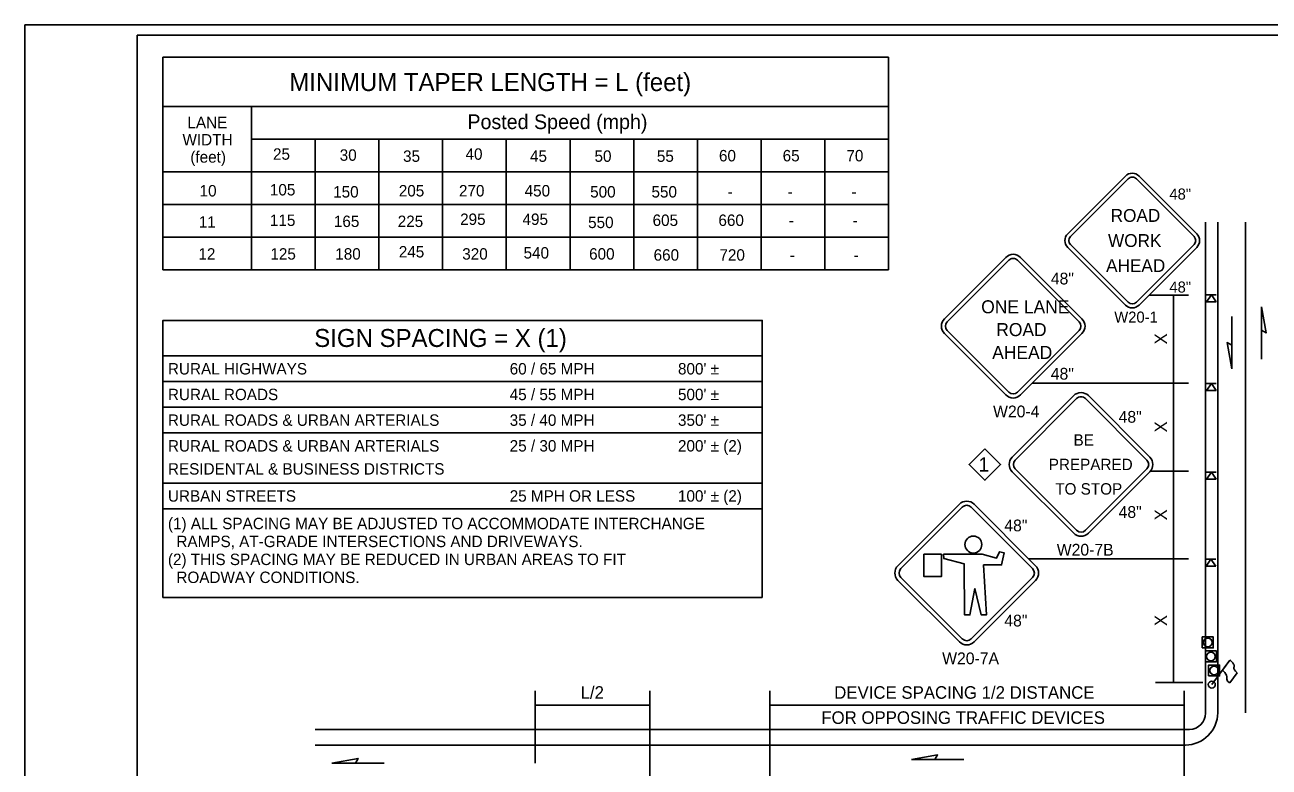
# Model space of a CAD drawing. Extents: x 99988 to 100172, y 99995 to 100047.
# Drawn here: x 99999.31 to 100006.94, y 100005.89 to 100010.44 of the extents above; entities that cross this region are included whole.
import ezdxf

# ---------------------------------------------------------------- set-up
doc = ezdxf.new("R2010")
doc.units = 0
for name, color, linetype in [('Default', 7, 'Continuous'), ('Level 15', 7, 'Continuous'), ('Level 20', 7, 'Continuous'), ('SH_DE_DetailBody1Text', 7, 'Continuous'), ('SH_GI_PlotLimits', 7, 'Continuous'), ('SH_GI_SheetBorder', 7, 'Continuous'), ('SH_GI_TrafficMvmntArrowRt1Lane', 7, 'Continuous'), ('SH_TI_MinTaperLength25to70Note', 7, 'Continuous'), ('SH_TI_SignSpacing35to70Note', 7, 'Continuous'), ('TR_SN_WarningSigns', 7, 'Continuous'), ('TR_WZ_FlaggingStation', 7, 'Continuous'), ('TR_WZ_TrafficSafetyCone', 7, 'Continuous'), ('TR_WZ_WorkZoneDetails', 7, 'Continuous')]:
    doc.layers.add(name, color=color, linetype=linetype)

msp = doc.modelspace()

# ---------------------------------------------------------------- linework, layer by layer
at = {"layer": 'Default'}
for p, q in [((100006.5586, 100008.7401), (100006.588, 100008.7825)), ((100006.5586, 100008.7825), (100006.6176, 100008.7825)), ((100006.5586, 100008.7401), (100006.6176, 100008.7401)), ((100006.6176, 100008.7401), (100006.588, 100008.7825)), ((100006.5586, 100008.1966), (100006.588, 100008.2389)), ((100006.5586, 100008.2389), (100006.6176, 100008.2389)), ((100006.5586, 100008.1966), (100006.6176, 100008.1966)), ((100006.6176, 100008.1966), (100006.588, 100008.2389)), ((100006.5586, 100007.653), (100006.588, 100007.6954)), ((100006.5586, 100007.6954), (100006.6176, 100007.6954)), ((100006.5586, 100007.653), (100006.6176, 100007.653)), ((100006.6176, 100007.653), (100006.588, 100007.6954)), ((100006.5553, 100007.1193), (100006.5848, 100007.1616)), ((100006.5553, 100007.1616), (100006.6143, 100007.1616)), ((100006.5553, 100007.1193), (100006.6143, 100007.1193)), ((100006.6143, 100007.1193), (100006.5848, 100007.1616))]:
    msp.add_line(p, q, dxfattribs=at)
at = {"layer": 'Level 15'}
for p, q in [((100006.355, 100008.781), (100006.355, 100008.5112)), ((100006.355, 100008.2414), (100006.355, 100008.5112)), ((100006.355, 100008.2414), (100006.355, 100007.9715)), ((100006.355, 100007.7017), (100006.355, 100007.9715)), ((100006.355, 100007.7017), (100006.355, 100007.4325)), ((100006.355, 100007.1633), (100006.355, 100007.4325)), ((100006.355, 100007.1633), (100006.355, 100006.7845)), ((100006.355, 100006.4057), (100006.355, 100006.7845)), ((100002.4418, 100006.2679), (100002.7935, 100006.2679)), ((100003.1451, 100006.2679), (100002.7935, 100006.2679)), ((100003.8812, 100006.2679), (100005.1513, 100006.2679)), ((100006.4214, 100006.2679), (100005.1513, 100006.2679))]:
    msp.add_line(p, q, dxfattribs=at)
at = {"layer": 'SH_DE_DetailBody1Text'}
msp.add_lwpolyline([(100005.1993, 100007.8395), (100005.2958, 100007.743), (100005.1993, 100007.6465), (100005.1027, 100007.743)], close=True, dxfattribs=at)
at = {"layer": 'SH_GI_PlotLimits'}
msp.add_lwpolyline([(99999.3125, 99999.9375), (100015.8125, 99999.9375), (100015.8125, 100010.4375), (99999.3125, 100010.4375)], close=True, dxfattribs=at)
at = {"layer": 'SH_GI_SheetBorder'}
for q in [(100000, 100000), (100015.75, 100010.375)]:
    msp.add_line((100000, 100010.375), q, dxfattribs=at)
at = {"layer": 'SH_GI_TrafficMvmntArrowRt1Lane'}
for p, q in [((100006.7126, 100008.4735), (100006.7126, 100008.6503)), ((100006.8951, 100008.5653), (100006.8951, 100008.3885)), ((100001.3398, 100005.9121), (100001.5166, 100005.9121)), ((100004.8932, 100005.9336), (100005.07, 100005.9336))]:
    msp.add_line(p, q, dxfattribs=at)
for points in [[(100006.8951, 100008.7095), (100006.9234, 100008.549), (100006.8951, 100008.5653)], [(100006.7126, 100008.3294), (100006.6844, 100008.4898), (100006.7126, 100008.4735)], [(100001.1957, 100005.9121), (100001.3561, 100005.9404), (100001.3398, 100005.9121)], [(100004.749, 100005.9336), (100004.9095, 100005.9618), (100004.8932, 100005.9336)]]:
    msp.add_lwpolyline(points, close=True, dxfattribs=at)
at = {"layer": 'SH_TI_MinTaperLength25to70Note'}
for p, q in [((100000.1587, 100009.9363), (100004.6087, 100009.9363)), ((100000.7018, 100009.4812), (100000.7018, 100009.9363)), ((100000.7018, 100009.7363), (100004.6087, 100009.7363)), ((100001.0925, 100009.7363), (100001.0925, 100008.9363)), ((100001.4832, 100009.7363), (100001.4832, 100008.9363)), ((100001.8739, 100009.7363), (100001.8739, 100008.9363)), ((100002.2646, 100009.7363), (100002.2646, 100008.9363)), ((100002.6553, 100009.7363), (100002.6553, 100008.9363)), ((100003.0459, 100009.7363), (100003.0459, 100008.9363)), ((100003.4366, 100009.7363), (100003.4366, 100008.9363)), ((100003.8273, 100009.7363), (100003.8273, 100008.9363)), ((100004.2179, 100009.7363), (100004.2179, 100008.9363)), ((100000.1587, 100009.5363), (100004.6087, 100009.5363)), ((100000.7018, 100009.4812), (100000.7018, 100008.9363)), ((100000.1587, 100009.3363), (100004.6087, 100009.3363)), ((100000.1587, 100009.1363), (100004.6087, 100009.1363))]:
    msp.add_line(p, q, dxfattribs=at)
at = {"layer": 'SH_TI_SignSpacing35to70Note'}
for p, q in [((100000.1587, 100010.2395), (100004.6087, 100010.2395)), ((100000.1587, 100009.4812), (100000.1587, 100010.2395)), ((100004.6087, 100010.2395), (100004.6087, 100008.9363)), ((100000.1587, 100009.4812), (100000.1587, 100008.9363)), ((100000.1587, 100008.9363), (100004.6087, 100008.9363)), ((100000.1587, 100008.4081), (100003.8342, 100008.4081)), ((100000.1587, 100008.2507), (100003.8342, 100008.2507)), ((100000.1587, 100008.0933), (100003.8342, 100008.0933)), ((100000.1587, 100007.9359), (100003.8342, 100007.9359)), ((100000.1587, 100007.6284), (100003.8342, 100007.6284)), ((100000.1587, 100007.471), (100003.8342, 100007.471)), ((100000.1587, 100006.9274), (100003.8342, 100006.9274))]:
    msp.add_line(p, q, dxfattribs=at)
for points in [[(100000.1587, 100008.4114), (100000.1587, 100008.6254), (100003.8342, 100008.6254), (100003.8342, 100008.4114)], [(100000.1587, 100006.9274), (100000.1587, 100008.4108)], [(100003.8342, 100008.4123), (100003.8342, 100006.9274)]]:
    msp.add_lwpolyline(points, dxfattribs=at)
at = {"layer": 'TR_SN_WarningSigns'}
for p, q in [((100005.7074, 100009.1576), (100006.0608, 100009.511)), ((100005.7242, 100009.1408), (100006.0776, 100009.4942)), ((100006.1281, 100009.4942), (100006.4815, 100009.1408)), ((100006.1449, 100009.511), (100006.4983, 100009.1576)), ((100006.0608, 100008.7201), (100005.7074, 100009.0735)), ((100006.0776, 100008.7369), (100005.7242, 100009.0903)), ((100006.4815, 100009.0903), (100006.1281, 100008.7369)), ((100006.4983, 100009.0735), (100006.1449, 100008.7201)), ((100004.9509, 100008.6355), (100005.3278, 100009.0125)), ((100004.9688, 100008.6176), (100005.3458, 100008.9945)), ((100005.3996, 100008.9945), (100005.7766, 100008.6176)), ((100005.4176, 100009.0125), (100005.7945, 100008.6355)), ((100005.3458, 100008.1868), (100004.9688, 100008.5637)), ((100005.7766, 100008.5637), (100005.3996, 100008.1868)), ((100005.3278, 100008.1688), (100004.9509, 100008.5458)), ((100005.7945, 100008.5458), (100005.4176, 100008.1688)), ((100005.3668, 100007.7879), (100005.7438, 100008.1648)), ((100005.3848, 100007.7699), (100005.7617, 100008.1469)), ((100005.8156, 100008.1469), (100006.1925, 100007.7699)), ((100005.8335, 100008.1648), (100006.2105, 100007.7879)), ((100005.7438, 100007.3212), (100005.3668, 100007.6981)), ((100005.7617, 100007.3391), (100005.3848, 100007.7161)), ((100006.1925, 100007.7161), (100005.8156, 100007.3391)), ((100006.2105, 100007.6981), (100005.8335, 100007.3212)), ((100004.6659, 100007.1221), (100005.0428, 100007.4991)), ((100005.1326, 100007.4991), (100005.5095, 100007.1221)), ((100004.6838, 100007.1042), (100005.0608, 100007.4812)), ((100005.1146, 100007.4812), (100005.4916, 100007.1042)), ((100005.0428, 100006.6555), (100004.6659, 100007.0324)), ((100005.0608, 100006.6734), (100004.6838, 100007.0503)), ((100005.4916, 100007.0503), (100005.1146, 100006.6734)), ((100005.5095, 100007.0324), (100005.1326, 100006.6555))]:
    msp.add_line(p, q, dxfattribs=at)
for points in [[(100004.8252, 100007.1927), (100004.8252, 100007.0555), (100004.9322, 100007.0555), (100004.9322, 100007.1927)], [(100004.9448, 100007.193), (100004.9464, 100007.1666), (100005.0717, 100007.1337), (100005.0744, 100006.8208), (100005.107, 100006.8208), (100005.138, 100006.9819), (100005.1771, 100006.8205), (100005.2086, 100006.8205), (100005.1907, 100007.1273), (100005.3019, 100007.1273), (100005.317, 100007.2018), (100005.2888, 100007.2072), (100005.2707, 100007.1691), (100005.1822, 100007.193)]]:
    msp.add_lwpolyline(points, close=True, dxfattribs=at)
msp.add_circle((100005.1285, 100007.2518), 0.0519, dxfattribs=at)
for centre, radius, start, end in [((100006.1029, 100009.4689), 0.0595, 44.99628, 134.99965), ((100006.1029, 100009.4689), 0.0357, 44.99628, 134.99965), ((100005.7495, 100009.1155), 0.0595, 134.99658, 224.99358), ((100005.7495, 100009.1155), 0.0357, 134.99658, 224.99358), ((100006.4562, 100009.1155), 0.0357, 314.99936, 44.99485), ((100006.4562, 100009.1155), 0.0595, 314.99936, 44.99485), ((100005.3727, 100008.9676), 0.0635, 44.99628, 134.99965), ((100005.3727, 100008.9676), 0.0381, 44.99628, 134.99965), ((100006.1028, 100008.7622), 0.0595, 225, 314.99958), ((100006.1028, 100008.7622), 0.0357, 225, 314.99958), ((100004.9958, 100008.5906), 0.0635, 134.99658, 224.99358), ((100005.7497, 100008.5906), 0.0635, 314.99936, 44.99485), ((100004.9958, 100008.5906), 0.0381, 134.99658, 224.99358), ((100005.7497, 100008.5906), 0.0381, 314.99936, 44.99485), ((100005.3727, 100008.2137), 0.0381, 225, 314.99958), ((100005.7886, 100008.1199), 0.0635, 44.99628, 134.99965), ((100005.3727, 100008.2137), 0.0635, 225, 314.99958), ((100005.7886, 100008.1199), 0.0381, 44.99628, 134.99965), ((100005.4117, 100007.743), 0.0635, 134.99658, 224.99358), ((100005.4117, 100007.743), 0.0381, 134.99658, 224.99358), ((100006.1656, 100007.743), 0.0381, 314.99936, 44.99485), ((100006.1656, 100007.743), 0.0635, 314.99936, 44.99485), ((100005.0877, 100007.4542), 0.0635, 44.99628, 134.99965), ((100005.0877, 100007.4542), 0.0381, 44.99628, 134.99965), ((100005.7886, 100007.3661), 0.0381, 225, 314.99958), ((100005.7886, 100007.3661), 0.0635, 225, 314.99958), ((100004.7107, 100007.0773), 0.0635, 134.99658, 224.99358), ((100005.4646, 100007.0773), 0.0635, 314.99936, 44.99485), ((100004.7107, 100007.0773), 0.0381, 134.99658, 224.99358), ((100005.4646, 100007.0773), 0.0381, 314.99936, 44.99485), ((100005.0877, 100006.7003), 0.0635, 225, 314.99958), ((100005.0877, 100006.7003), 0.0381, 225, 314.99958)]:
    msp.add_arc(centre, radius, start, end, dxfattribs=at)
at = {"layer": 'TR_WZ_FlaggingStation'}
for p, q in [((100006.5906, 100006.3933), (100006.7016, 100006.5433)), ((100006.6566, 100006.4824), (100006.7018, 100006.5435)), ((100006.6566, 100006.4824), (100006.6566, 100006.4824)), ((100006.7468, 100006.4658), (100006.7005, 100006.4032))]:
    msp.add_line(p, q, dxfattribs=at)
for points in [[(100006.7018, 100006.5435), (100006.7046, 100006.5408), (100006.7137, 100006.533), (100006.7202, 100006.526), (100006.7237, 100006.5194), (100006.727, 100006.5139), (100006.728, 100006.5081), (100006.7279, 100006.5022), (100006.7261, 100006.4985), (100006.7262, 100006.4915), (100006.7299, 100006.4836), (100006.7352, 100006.4766), (100006.7468, 100006.4658)], [(100006.7005, 100006.4032), (100006.6963, 100006.4067), (100006.6877, 100006.4152), (100006.6823, 100006.4263), (100006.682, 100006.4345), (100006.6832, 100006.4417), (100006.6816, 100006.4509), (100006.6774, 100006.4581), (100006.6698, 100006.4679), (100006.6566, 100006.4824)]]:
    msp.add_lwpolyline(points, dxfattribs=at)
msp.add_circle((100006.5906, 100006.3933), 0.0214, dxfattribs=at)
at = {"layer": 'TR_WZ_TrafficSafetyCone'}
for points in [[(100006.5322, 100006.6185), (100006.599, 100006.6185), (100006.599, 100006.6853), (100006.5322, 100006.6853)], [(100006.5517, 100006.5325), (100006.6186, 100006.5325), (100006.6186, 100006.5993), (100006.5517, 100006.5993)], [(100006.5713, 100006.4465), (100006.6381, 100006.4465), (100006.6381, 100006.5133), (100006.5713, 100006.5133)]]:
    msp.add_lwpolyline(points, close=True, dxfattribs=at)
for centre in [(100006.5656, 100006.6519), (100006.5851, 100006.5659), (100006.6047, 100006.4799)]:
    msp.add_circle(centre, 0.0268, dxfattribs=at)
at = {"layer": 'TR_WZ_WorkZoneDetails'}
for p, q in [((100006.5524, 100006.2179), (100006.5524, 100009.2274)), ((100006.6267, 100006.2209), (100006.6267, 100009.2274)), ((100006.797, 100006.2209), (100006.797, 100009.2274)), ((100006.4486, 100008.781), (100006.2059, 100008.781)), ((100006.4486, 100008.2414), (100005.4901, 100008.2414)), ((100006.4486, 100007.7017), (100006.2138, 100007.7017)), ((100006.4486, 100007.1633), (100005.4684, 100007.1633)), ((100002.4418, 100005.9119), (100002.4418, 100006.3559)), ((100003.1451, 100005.7776), (100003.1451, 100006.3559)), ((100003.8812, 100005.6997), (100003.8812, 100006.3559)), ((100006.5347, 100006.4057), (100006.245, 100006.4057)), ((100006.4214, 100005.7046), (100006.4214, 100006.3559)), ((100001.0926, 100006.1188), (100002.7834, 100006.1188)), ((100002.281, 100006.1188), (100006.4533, 100006.1188)), ((100001.0926, 100006.0228), (100002.7834, 100006.0228)), ((100002.281, 100006.0228), (100006.4285, 100006.0228))]:
    msp.add_line(p, q, dxfattribs=at)
for centre, radius in [((100006.4285, 100006.2209), 0.1982), ((100006.4533, 100006.2179), 0.0991)]:
    msp.add_arc(centre, radius, 270, 360, dxfattribs=at)

# ---------------------------------------------------------------- texts
at = {"layer": 'Level 20'}
for s, rotation, p in [('X', 90, (100006.3165, 100008.4785)), ('X', 90, (100006.3165, 100007.9389)), ('X', 90, (100006.3165, 100007.3998)), ('X', 90, (100006.3165, 100006.7518)), ('L/2', 360, (100002.7201, 100006.3064)), ('DEVICE SPACING 1/2 DISTANCE', 360, (100004.2752, 100006.3064))]:
    msp.add_text(s, height=0.077, rotation=rotation, dxfattribs=at).set_placement(p)
msp.add_text('FOR OPPOSING TRAFFIC DEVICES', height=0.077, dxfattribs=at).set_placement((100004.1962, 100006.1524))
at = {"layer": 'SH_DE_DetailBody1Text'}
msp.add_text('1', height=0.088, dxfattribs=at).set_placement((100005.1607, 100007.699))
at = {"layer": 'SH_TI_MinTaperLength25to70Note'}
for s, height, p in [('MINIMUM TAPER LENGTH = L (feet)', 0.11, (100000.9337, 100010.0319)), ('LANE', 0.07, (100000.3093, 100009.8042)), ('Posted Speed (mph)', 0.09, (100002.0262, 100009.7987)), ('WIDTH', 0.07, (100000.279, 100009.6986)), ('(feet)', 0.07, (100000.3271, 100009.593)), ('25', 0.07, (100000.834, 100009.6108)), ('30', 0.07, (100001.243, 100009.6046)), ('35', 0.07, (100001.6315, 100009.598)), ('40', 0.07, (100002.0144, 100009.6108)), ('45', 0.07, (100002.4098, 100009.598)), ('50', 0.07, (100002.8054, 100009.598)), ('55', 0.07, (100003.1877, 100009.598)), ('60', 0.07, (100003.5685, 100009.6008)), ('65', 0.07, (100003.9592, 100009.6008)), ('70', 0.07, (100004.3499, 100009.6008)), ('10', 0.07, (100000.3839, 100009.3858)), ('105', 0.07, (100000.8148, 100009.392)), ('150', 0.07, (100001.2028, 100009.3792)), ('205', 0.07, (100001.6053, 100009.3858)), ('270', 0.07, (100001.9743, 100009.3858)), ('450', 0.07, (100002.3769, 100009.3858)), ('500', 0.07, (100002.7787, 100009.3792)), ('550', 0.07, (100003.1548, 100009.3792)), ('-', 0.07, (100003.6213, 100009.3792)), ('-', 0.07, (100003.99, 100009.3792)), ('-', 0.07, (100004.3809, 100009.3792)), ('11', 0.07, (100000.3788, 100009.1946)), ('115', 0.07, (100000.815, 100009.205)), ('165', 0.07, (100001.2072, 100009.1984)), ('225', 0.07, (100001.5987, 100009.1984)), ('295', 0.07, (100001.9813, 100009.2111)), ('495', 0.07, (100002.364, 100009.2111)), ('550', 0.07, (100002.7661, 100009.1919)), ('605', 0.07, (100003.1615, 100009.205)), ('660', 0.07, (100003.5652, 100009.205)), ('-', 0.07, (100003.9967, 100009.205)), ('-', 0.07, (100004.3876, 100009.205)), ('12', 0.07, (100000.3765, 100008.9986)), ('125', 0.07, (100000.8179, 100008.9986)), ('180', 0.07, (100001.2159, 100008.9986)), ('245', 0.07, (100001.6053, 100009.0117)), ('320', 0.07, (100001.9943, 100008.9986)), ('540', 0.07, (100002.3704, 100009.0052)), ('600', 0.07, (100002.7723, 100008.9986)), ('660', 0.07, (100003.1678, 100008.9921)), ('720', 0.07, (100003.5714, 100008.9921)), ('-', 0.07, (100004.0029, 100008.9921)), ('-', 0.07, (100004.3939, 100008.9921))]:
    msp.add_text(s, height=height, dxfattribs=at).set_placement(p)
at = {"layer": 'SH_TI_SignSpacing35to70Note'}
for s, height, p in [('SIGN SPACING = X (1)', 0.11, (100001.0868, 100008.4631)), ('RURAL HIGHWAYS', 0.07, (100000.1897, 100008.2944)), ('60 / 65 MPH', 0.07, (100002.2853, 100008.2944)), ("800' ±", 0.07, (100003.3173, 100008.2944)), ('RURAL ROADS', 0.07, (100000.1897, 100008.137)), ('45 / 55 MPH', 0.07, (100002.2853, 100008.137)), ("500' ±", 0.07, (100003.3173, 100008.137)), ('RURAL ROADS & URBAN ARTERIALS', 0.07, (100000.1897, 100007.9796)), ('35 / 40 MPH', 0.07, (100002.2853, 100007.9796)), ("350' ± ", 0.07, (100003.3173, 100007.9796)), ('RURAL ROADS & URBAN ARTERIALS', 0.07, (100000.1897, 100007.8219)), ('25 / 30 MPH', 0.07, (100002.2853, 100007.8221)), ("200' ± (2)", 0.07, (100003.3173, 100007.8221)), ('RESIDENTAL & BUSINESS DISTRICTS', 0.07, (100000.1897, 100007.6807)), ('URBAN STREETS', 0.07, (100000.1897, 100007.5147)), ('25 MPH OR LESS', 0.07, (100002.2853, 100007.5147)), ("100' ± (2) ", 0.07, (100003.3173, 100007.5147)), ('(1) ALL SPACING MAY BE ADJUSTED TO ACCOMMODATE INTERCHANGE ', 0.07, (100000.1896, 100007.346)), ('  RAMPS, AT-GRADE INTERSECTIONS AND DRIVEWAYS.', 0.07, (100000.1896, 100007.236)), ('(2) THIS SPACING MAY BE REDUCED IN URBAN AREAS TO FIT  ', 0.07, (100000.1896, 100007.126)), ('  ROADWAY CONDITIONS.', 0.07, (100000.1896, 100007.016))]:
    msp.add_text(s, height=height, dxfattribs=at).set_placement(p)
at = {"layer": 'TR_SN_WarningSigns'}
for s, height, p in [('48"', 0.06768, (100006.3306, 100009.3667)), ('ROAD', 0.0787, (100005.9704, 100009.2299)), ('WORK', 0.0787, (100005.9542, 100009.0762)), ('AHEAD', 0.0787, (100005.9424, 100008.9226)), ('48"', 0.07219, (100005.6034, 100008.8462)), ('48"', 0.06768, (100006.3306, 100008.7967)), ('ONE LANE', 0.07995, (100005.1766, 100008.6694)), ('W20-1', 0.06768, (100005.9927, 100008.6123)), ('ROAD', 0.07995, (100005.2689, 100008.5295)), ('AHEAD', 0.07995, (100005.244, 100008.3896)), ('48"', 0.07219, (100005.6033, 100008.2629)), ('W20-4', 0.07219, (100005.2493, 100008.0316)), ('48"', 0.07219, (100006.0192, 100007.9986)), ('BE', 0.06996, (100005.7428, 100007.8579)), ('PREPARED', 0.06996, (100005.5907, 100007.708)), ('TO STOP', 0.06996, (100005.6305, 100007.5581)), ('48"', 0.07219, (100006.0192, 100007.4152)), ('48"', 0.07219, (100005.3183, 100007.3329)), ('W20-7B', 0.07219, (100005.6399, 100007.184)), ('48"', 0.07219, (100005.3183, 100006.7495)), ('W20-7A', 0.07219, (100004.9372, 100006.5183))]:
    msp.add_text(s, height=height, dxfattribs=at).set_placement(p)

doc.saveas('drawing.dxf')
